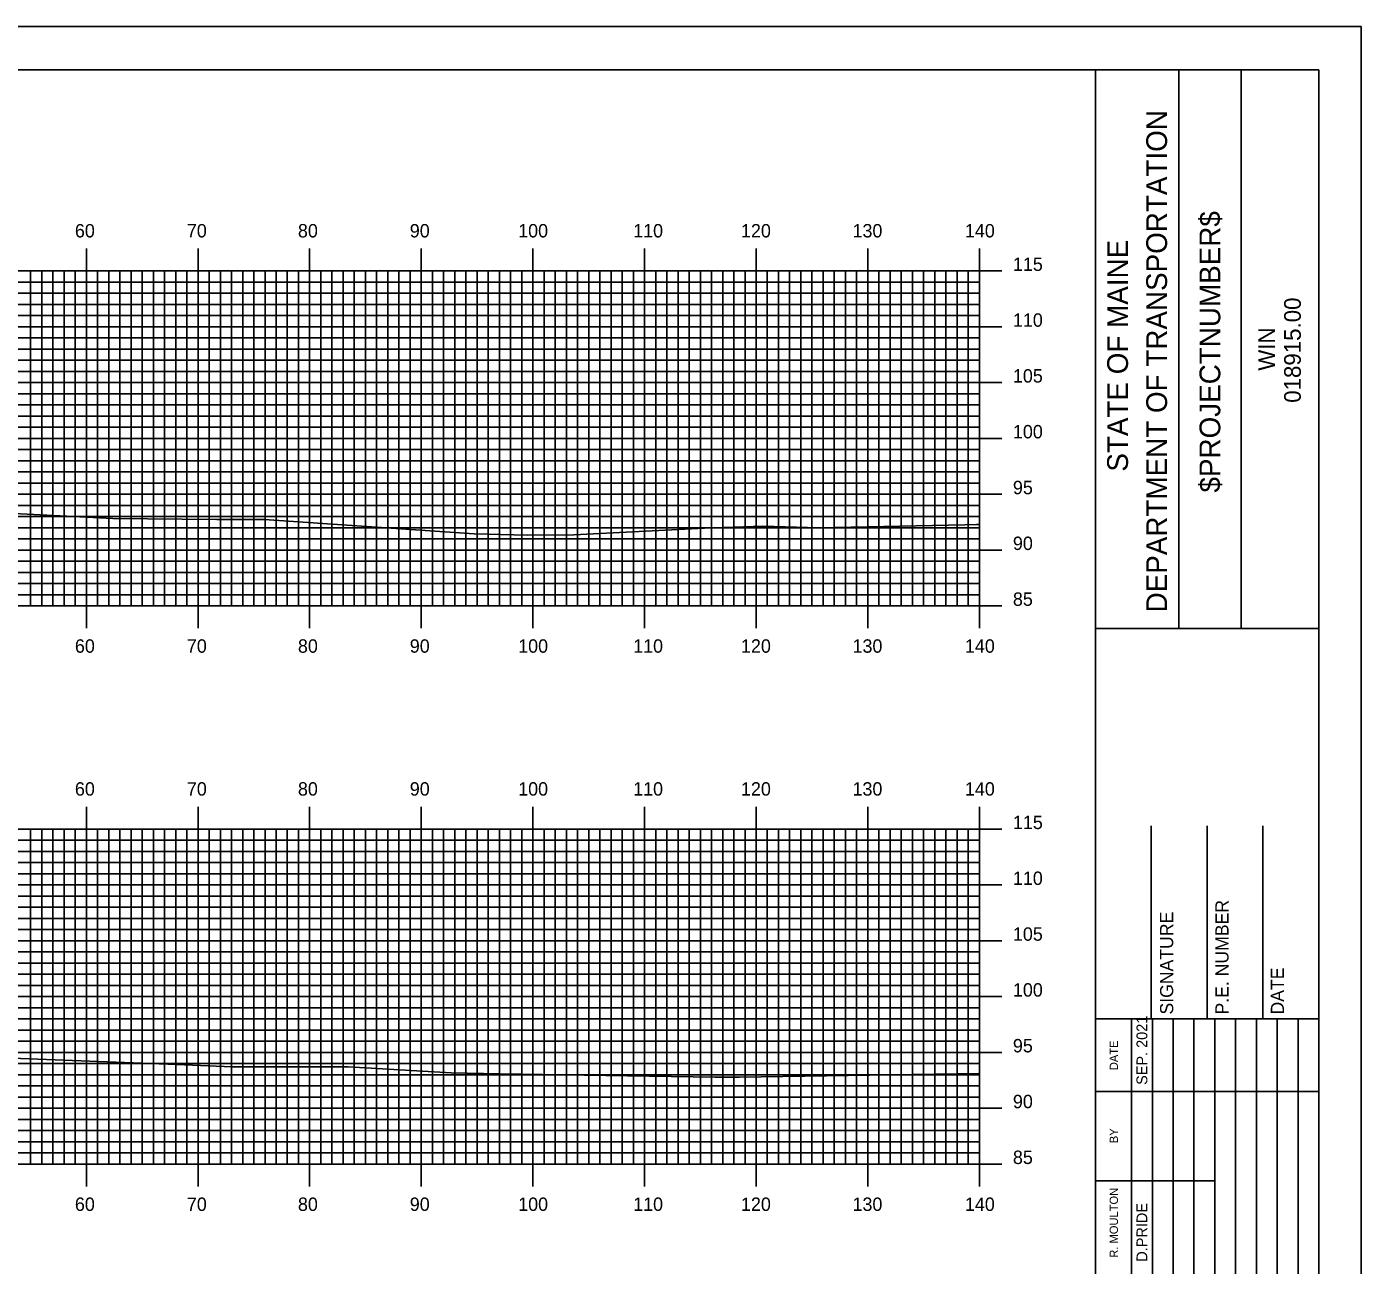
# Model space of a CAD drawing. Extents: x 1761004 to 1761347, y 442591 to 442811.
# Drawn here: x 1761224.4 to 1761343.9, y 442699.6 to 442810.5 of the extents above; entities that cross this region are included whole.
import ezdxf

# ---------------------------------------------------------------- set-up
doc = ezdxf.new("R2010")
doc.units = 0
for name, color, linetype in [('BORDER', 7, 'Continuous'), ('H_V ANNOTATION', 7, 'Continuous'), ('MAJOR', 7, 'Continuous'), ('MINOR', 7, 'Continuous'), ('PLOT BOUNDARY', 7, 'Continuous'), ('S_Roadway_Centerline', 7, 'Continuous')]:
    doc.layers.add(name, color=color, linetype=linetype)

msp = doc.modelspace()

# ---------------------------------------------------------------- linework, layer by layer
at = {"layer": 'BORDER'}
for p, q in [((1761320.13, 442596.67), (1761320.13, 442806.67)), ((1761327.58, 442756.66), (1761327.58, 442806.66)), ((1761333.17, 442756.66), (1761333.17, 442806.66)), ((1761320.13, 442756.65), (1761340.13, 442756.65)), ((1761325.13, 442721.67), (1761325.13, 442738.97)), ((1761330.13, 442721.67), (1761330.13, 442738.97)), ((1761335.13, 442721.67), (1761335.13, 442738.97)), ((1761320.13, 442721.67), (1761340.13, 442721.67))]:
    msp.add_line(p, q, dxfattribs=at)
msp.add_lwpolyline([(1761020.13, 442596.67), (1761340.13, 442596.67), (1761340.13, 442806.67), (1761020.13, 442806.67)], close=True, dxfattribs=at)
for points in [[(1761323.36, 442715.17), (1761323.36, 442721.67)], [(1761325.22, 442686.68), (1761325.22, 442721.67)], [(1761327.09, 442721.67), (1761327.09, 442686.68)], [(1761328.95, 442686.68), (1761328.95, 442721.67)], [(1761330.81, 442686.68), (1761330.81, 442721.67)], [(1761332.68, 442686.68), (1761332.68, 442721.67)], [(1761334.54, 442686.68), (1761334.54, 442721.67)], [(1761336.4, 442686.68), (1761336.4, 442721.67)], [(1761338.27, 442686.68), (1761338.27, 442721.67)], [(1761323.36, 442686.68), (1761323.36, 442720.26)], [(1761320.13, 442715.17), (1761340.13, 442715.17)], [(1761320.13, 442707.17), (1761323.36, 442707.17)], [(1761323.36, 442707.17), (1761330.81, 442707.17)]]:
    msp.add_lwpolyline(points, dxfattribs=at)
at = {"layer": 'MAJOR'}
for p, q in [((1761229.73, 442790.67), (1761229.73, 442788.67)), ((1761239.73, 442790.67), (1761239.73, 442788.67)), ((1761249.73, 442790.67), (1761249.73, 442788.67)), ((1761259.73, 442790.67), (1761259.73, 442788.67)), ((1761269.73, 442790.67), (1761269.73, 442788.67)), ((1761279.73, 442790.67), (1761279.73, 442788.67)), ((1761289.73, 442790.67), (1761289.73, 442788.67)), ((1761299.73, 442790.67), (1761299.73, 442788.67)), ((1761309.73, 442790.67), (1761309.73, 442788.67)), ((1761029.73, 442788.67), (1761309.73, 442788.67)), ((1761029.73, 442788.67), (1761309.73, 442788.67)), ((1761229.73, 442758.67), (1761229.73, 442788.67)), ((1761239.73, 442758.67), (1761239.73, 442788.67)), ((1761249.73, 442758.67), (1761249.73, 442788.67)), ((1761259.73, 442758.67), (1761259.73, 442788.67)), ((1761269.73, 442758.67), (1761269.73, 442788.67)), ((1761279.73, 442758.67), (1761279.73, 442788.67)), ((1761289.73, 442758.67), (1761289.73, 442788.67)), ((1761299.73, 442758.67), (1761299.73, 442788.67)), ((1761311.73, 442788.67), (1761307.72, 442788.67)), ((1761309.73, 442758.67), (1761309.73, 442788.67)), ((1761309.73, 442758.67), (1761309.73, 442788.67)), ((1761029.73, 442783.67), (1761309.73, 442783.67)), ((1761311.73, 442783.67), (1761307.72, 442783.67)), ((1761029.73, 442778.67), (1761309.73, 442778.67)), ((1761311.73, 442778.67), (1761307.72, 442778.67)), ((1761029.73, 442773.67), (1761309.73, 442773.67)), ((1761311.73, 442773.67), (1761307.72, 442773.67)), ((1761029.73, 442768.67), (1761309.73, 442768.67)), ((1761311.73, 442768.67), (1761307.72, 442768.67)), ((1761029.73, 442763.67), (1761309.73, 442763.67)), ((1761311.73, 442763.67), (1761307.72, 442763.67)), ((1761029.73, 442758.67), (1761309.73, 442758.67)), ((1761029.73, 442758.67), (1761309.73, 442758.67)), ((1761229.73, 442756.66), (1761229.73, 442758.67)), ((1761239.73, 442756.66), (1761239.73, 442758.67)), ((1761249.73, 442756.66), (1761249.73, 442758.67)), ((1761259.73, 442756.66), (1761259.73, 442758.67)), ((1761269.73, 442756.66), (1761269.73, 442758.67)), ((1761279.73, 442756.66), (1761279.73, 442758.67)), ((1761289.73, 442756.66), (1761289.73, 442758.67)), ((1761299.73, 442756.66), (1761299.73, 442758.67)), ((1761311.73, 442758.67), (1761307.72, 442758.67)), ((1761309.73, 442756.66), (1761309.73, 442758.67)), ((1761229.73, 442740.67), (1761229.73, 442738.67)), ((1761239.73, 442740.67), (1761239.73, 442738.67)), ((1761249.73, 442740.67), (1761249.73, 442738.67)), ((1761259.73, 442740.67), (1761259.73, 442738.67)), ((1761269.73, 442740.67), (1761269.73, 442738.67)), ((1761279.73, 442740.67), (1761279.73, 442738.67)), ((1761289.73, 442740.67), (1761289.73, 442738.67)), ((1761299.73, 442740.67), (1761299.73, 442738.67)), ((1761309.73, 442740.67), (1761309.73, 442738.67)), ((1761029.73, 442738.67), (1761309.73, 442738.67)), ((1761029.73, 442738.67), (1761309.73, 442738.67)), ((1761229.73, 442708.67), (1761229.73, 442738.67)), ((1761239.73, 442708.67), (1761239.73, 442738.67)), ((1761249.73, 442708.67), (1761249.73, 442738.67)), ((1761259.73, 442708.67), (1761259.73, 442738.67)), ((1761269.73, 442708.67), (1761269.73, 442738.67)), ((1761279.73, 442708.67), (1761279.73, 442738.67)), ((1761289.73, 442708.67), (1761289.73, 442738.67)), ((1761299.73, 442708.67), (1761299.73, 442738.67)), ((1761311.73, 442738.67), (1761307.72, 442738.67)), ((1761309.73, 442708.67), (1761309.73, 442738.67)), ((1761309.73, 442708.67), (1761309.73, 442738.67)), ((1761029.73, 442733.67), (1761309.73, 442733.67)), ((1761311.73, 442733.67), (1761307.72, 442733.67)), ((1761029.73, 442728.67), (1761309.73, 442728.67)), ((1761311.73, 442728.67), (1761307.72, 442728.67)), ((1761029.73, 442723.67), (1761309.73, 442723.67)), ((1761311.73, 442723.67), (1761307.72, 442723.67)), ((1761029.73, 442718.67), (1761309.73, 442718.67)), ((1761311.73, 442718.67), (1761307.72, 442718.67)), ((1761029.73, 442713.67), (1761309.73, 442713.67)), ((1761311.73, 442713.67), (1761307.72, 442713.67)), ((1761029.73, 442708.67), (1761309.73, 442708.67)), ((1761029.73, 442708.67), (1761309.73, 442708.67)), ((1761229.73, 442706.66), (1761229.73, 442708.67)), ((1761239.73, 442706.66), (1761239.73, 442708.67)), ((1761249.73, 442706.66), (1761249.73, 442708.67)), ((1761259.73, 442706.66), (1761259.73, 442708.67)), ((1761269.73, 442706.66), (1761269.73, 442708.67)), ((1761279.73, 442706.66), (1761279.73, 442708.67)), ((1761289.73, 442706.66), (1761289.73, 442708.67)), ((1761299.73, 442706.66), (1761299.73, 442708.67)), ((1761311.73, 442708.67), (1761307.72, 442708.67)), ((1761309.73, 442706.66), (1761309.73, 442708.67))]:
    msp.add_line(p, q, dxfattribs=at)
at = {"layer": 'MINOR'}
for p, q in [((1761224.73, 442758.67), (1761224.73, 442788.67)), ((1761225.73, 442758.67), (1761225.73, 442788.67)), ((1761226.73, 442758.67), (1761226.73, 442788.67)), ((1761227.73, 442758.67), (1761227.73, 442788.67)), ((1761228.73, 442758.67), (1761228.73, 442788.67)), ((1761230.73, 442758.67), (1761230.73, 442788.67)), ((1761231.73, 442758.67), (1761231.73, 442788.67)), ((1761232.73, 442758.67), (1761232.73, 442788.67)), ((1761233.73, 442758.67), (1761233.73, 442788.67)), ((1761234.73, 442758.67), (1761234.73, 442788.67)), ((1761235.73, 442758.67), (1761235.73, 442788.67)), ((1761236.73, 442758.67), (1761236.73, 442788.67)), ((1761237.73, 442758.67), (1761237.73, 442788.67)), ((1761238.73, 442758.67), (1761238.73, 442788.67)), ((1761240.73, 442758.67), (1761240.73, 442788.67)), ((1761241.73, 442758.67), (1761241.73, 442788.67)), ((1761242.73, 442758.67), (1761242.73, 442788.67)), ((1761243.73, 442758.67), (1761243.73, 442788.67)), ((1761244.73, 442758.67), (1761244.73, 442788.67)), ((1761245.73, 442758.67), (1761245.73, 442788.67)), ((1761246.73, 442758.67), (1761246.73, 442788.67)), ((1761247.73, 442758.67), (1761247.73, 442788.67)), ((1761248.73, 442758.67), (1761248.73, 442788.67)), ((1761250.73, 442758.67), (1761250.73, 442788.67)), ((1761251.73, 442758.67), (1761251.73, 442788.67)), ((1761252.73, 442758.67), (1761252.73, 442788.67)), ((1761253.73, 442758.67), (1761253.73, 442788.67)), ((1761254.73, 442758.67), (1761254.73, 442788.67)), ((1761255.73, 442758.67), (1761255.73, 442788.67)), ((1761256.73, 442758.67), (1761256.73, 442788.67)), ((1761257.73, 442758.67), (1761257.73, 442788.67)), ((1761258.73, 442758.67), (1761258.73, 442788.67)), ((1761260.73, 442758.67), (1761260.73, 442788.67)), ((1761261.73, 442758.67), (1761261.73, 442788.67)), ((1761262.73, 442758.67), (1761262.73, 442788.67)), ((1761263.73, 442758.67), (1761263.73, 442788.67)), ((1761264.73, 442758.67), (1761264.73, 442788.67)), ((1761265.73, 442758.67), (1761265.73, 442788.67)), ((1761266.73, 442758.67), (1761266.73, 442788.67)), ((1761267.73, 442758.67), (1761267.73, 442788.67)), ((1761268.73, 442758.67), (1761268.73, 442788.67)), ((1761270.73, 442758.67), (1761270.73, 442788.67)), ((1761271.73, 442758.67), (1761271.73, 442788.67)), ((1761272.73, 442758.67), (1761272.73, 442788.67)), ((1761273.73, 442758.67), (1761273.73, 442788.67)), ((1761274.73, 442758.67), (1761274.73, 442788.67)), ((1761275.73, 442758.67), (1761275.73, 442788.67)), ((1761276.73, 442758.67), (1761276.73, 442788.67)), ((1761277.73, 442758.67), (1761277.73, 442788.67)), ((1761278.73, 442758.67), (1761278.73, 442788.67)), ((1761280.73, 442758.67), (1761280.73, 442788.67)), ((1761281.73, 442758.67), (1761281.73, 442788.67)), ((1761282.73, 442758.67), (1761282.73, 442788.67)), ((1761283.73, 442758.67), (1761283.73, 442788.67)), ((1761284.73, 442758.67), (1761284.73, 442788.67)), ((1761285.73, 442758.67), (1761285.73, 442788.67)), ((1761286.73, 442758.67), (1761286.73, 442788.67)), ((1761287.73, 442758.67), (1761287.73, 442788.67)), ((1761288.73, 442758.67), (1761288.73, 442788.67)), ((1761290.73, 442758.67), (1761290.73, 442788.67)), ((1761291.73, 442758.67), (1761291.73, 442788.67)), ((1761292.73, 442758.67), (1761292.73, 442788.67)), ((1761293.73, 442758.67), (1761293.73, 442788.67)), ((1761294.73, 442758.67), (1761294.73, 442788.67)), ((1761295.73, 442758.67), (1761295.73, 442788.67)), ((1761296.73, 442758.67), (1761296.73, 442788.67)), ((1761297.73, 442758.67), (1761297.73, 442788.67)), ((1761298.73, 442758.67), (1761298.73, 442788.67)), ((1761300.73, 442758.67), (1761300.73, 442788.67)), ((1761301.73, 442758.67), (1761301.73, 442788.67)), ((1761302.73, 442758.67), (1761302.73, 442788.67)), ((1761303.73, 442758.67), (1761303.73, 442788.67)), ((1761304.73, 442758.67), (1761304.73, 442788.67)), ((1761305.73, 442758.67), (1761305.73, 442788.67)), ((1761306.73, 442758.67), (1761306.73, 442788.67)), ((1761307.73, 442758.67), (1761307.73, 442788.67)), ((1761308.73, 442758.67), (1761308.73, 442788.67)), ((1761029.73, 442787.67), (1761309.73, 442787.67)), ((1761309.73, 442787.67), (1761307.72, 442787.67)), ((1761029.73, 442786.67), (1761309.73, 442786.67)), ((1761309.73, 442786.67), (1761307.72, 442786.67)), ((1761029.73, 442785.67), (1761309.73, 442785.67)), ((1761309.73, 442785.67), (1761307.72, 442785.67)), ((1761029.73, 442784.67), (1761309.73, 442784.67)), ((1761309.73, 442784.67), (1761307.72, 442784.67)), ((1761029.73, 442782.67), (1761309.73, 442782.67)), ((1761309.73, 442782.67), (1761307.72, 442782.67)), ((1761029.73, 442781.67), (1761309.73, 442781.67)), ((1761309.73, 442781.67), (1761307.72, 442781.67)), ((1761029.73, 442780.67), (1761309.73, 442780.67)), ((1761309.73, 442780.67), (1761307.72, 442780.67)), ((1761029.73, 442779.67), (1761309.73, 442779.67)), ((1761309.73, 442779.67), (1761307.72, 442779.67)), ((1761029.73, 442777.67), (1761309.73, 442777.67)), ((1761309.73, 442777.67), (1761307.72, 442777.67)), ((1761029.73, 442776.67), (1761309.73, 442776.67)), ((1761309.73, 442776.67), (1761307.72, 442776.67)), ((1761029.73, 442775.67), (1761309.73, 442775.67)), ((1761309.73, 442775.67), (1761307.72, 442775.67)), ((1761029.73, 442774.67), (1761309.73, 442774.67)), ((1761309.73, 442774.67), (1761307.72, 442774.67)), ((1761029.73, 442772.67), (1761309.73, 442772.67)), ((1761029.73, 442771.67), (1761309.73, 442771.67)), ((1761309.73, 442772.67), (1761307.72, 442772.67)), ((1761309.73, 442771.67), (1761307.72, 442771.67)), ((1761029.73, 442770.67), (1761309.73, 442770.67)), ((1761309.73, 442770.67), (1761307.72, 442770.67)), ((1761029.73, 442769.67), (1761309.73, 442769.67)), ((1761309.73, 442769.67), (1761307.72, 442769.67)), ((1761029.73, 442767.67), (1761309.73, 442767.67)), ((1761309.73, 442767.67), (1761307.72, 442767.67)), ((1761029.73, 442766.67), (1761309.73, 442766.67)), ((1761029.73, 442765.67), (1761309.73, 442765.67)), ((1761309.73, 442766.67), (1761307.72, 442766.67)), ((1761309.73, 442765.67), (1761307.72, 442765.67)), ((1761029.73, 442764.67), (1761309.73, 442764.67)), ((1761309.73, 442764.67), (1761307.72, 442764.67)), ((1761029.73, 442762.67), (1761309.73, 442762.67)), ((1761309.73, 442762.67), (1761307.72, 442762.67)), ((1761029.73, 442761.67), (1761309.73, 442761.67)), ((1761309.73, 442761.67), (1761307.72, 442761.67)), ((1761029.73, 442760.67), (1761309.73, 442760.67)), ((1761029.73, 442759.67), (1761309.73, 442759.67)), ((1761309.73, 442760.67), (1761307.72, 442760.67)), ((1761309.73, 442759.67), (1761307.72, 442759.67)), ((1761224.73, 442708.67), (1761224.73, 442738.67)), ((1761225.73, 442708.67), (1761225.73, 442738.67)), ((1761226.73, 442708.67), (1761226.73, 442738.67)), ((1761227.73, 442708.67), (1761227.73, 442738.67)), ((1761228.73, 442708.67), (1761228.73, 442738.67)), ((1761230.73, 442708.67), (1761230.73, 442738.67)), ((1761231.73, 442708.67), (1761231.73, 442738.67)), ((1761232.73, 442708.67), (1761232.73, 442738.67)), ((1761233.73, 442708.67), (1761233.73, 442738.67)), ((1761234.73, 442708.67), (1761234.73, 442738.67)), ((1761235.73, 442708.67), (1761235.73, 442738.67)), ((1761236.73, 442708.67), (1761236.73, 442738.67)), ((1761237.73, 442708.67), (1761237.73, 442738.67)), ((1761238.73, 442708.67), (1761238.73, 442738.67)), ((1761240.73, 442708.67), (1761240.73, 442738.67)), ((1761241.73, 442708.67), (1761241.73, 442738.67)), ((1761242.73, 442708.67), (1761242.73, 442738.67)), ((1761243.73, 442708.67), (1761243.73, 442738.67)), ((1761244.73, 442708.67), (1761244.73, 442738.67)), ((1761245.73, 442708.67), (1761245.73, 442738.67)), ((1761246.73, 442708.67), (1761246.73, 442738.67)), ((1761247.73, 442708.67), (1761247.73, 442738.67)), ((1761248.73, 442708.67), (1761248.73, 442738.67)), ((1761250.73, 442708.67), (1761250.73, 442738.67)), ((1761251.73, 442708.67), (1761251.73, 442738.67)), ((1761252.73, 442708.67), (1761252.73, 442738.67)), ((1761253.73, 442708.67), (1761253.73, 442738.67)), ((1761254.73, 442708.67), (1761254.73, 442738.67)), ((1761255.73, 442708.67), (1761255.73, 442738.67)), ((1761256.73, 442708.67), (1761256.73, 442738.67)), ((1761257.73, 442708.67), (1761257.73, 442738.67)), ((1761258.73, 442708.67), (1761258.73, 442738.67)), ((1761260.73, 442708.67), (1761260.73, 442738.67)), ((1761261.73, 442708.67), (1761261.73, 442738.67)), ((1761262.73, 442708.67), (1761262.73, 442738.67)), ((1761263.73, 442708.67), (1761263.73, 442738.67)), ((1761264.73, 442708.67), (1761264.73, 442738.67)), ((1761265.73, 442708.67), (1761265.73, 442738.67)), ((1761266.73, 442708.67), (1761266.73, 442738.67)), ((1761267.73, 442708.67), (1761267.73, 442738.67)), ((1761268.73, 442708.67), (1761268.73, 442738.67)), ((1761270.73, 442708.67), (1761270.73, 442738.67)), ((1761271.73, 442708.67), (1761271.73, 442738.67)), ((1761272.73, 442708.67), (1761272.73, 442738.67)), ((1761273.73, 442708.67), (1761273.73, 442738.67)), ((1761274.73, 442708.67), (1761274.73, 442738.67)), ((1761275.73, 442708.67), (1761275.73, 442738.67)), ((1761276.73, 442708.67), (1761276.73, 442738.67)), ((1761277.73, 442708.67), (1761277.73, 442738.67)), ((1761278.73, 442708.67), (1761278.73, 442738.67)), ((1761280.73, 442708.67), (1761280.73, 442738.67)), ((1761281.73, 442708.67), (1761281.73, 442738.67)), ((1761282.73, 442708.67), (1761282.73, 442738.67)), ((1761283.73, 442708.67), (1761283.73, 442738.67)), ((1761284.73, 442708.67), (1761284.73, 442738.67)), ((1761285.73, 442708.67), (1761285.73, 442738.67)), ((1761286.73, 442708.67), (1761286.73, 442738.67)), ((1761287.73, 442708.67), (1761287.73, 442738.67)), ((1761288.73, 442708.67), (1761288.73, 442738.67)), ((1761290.73, 442708.67), (1761290.73, 442738.67)), ((1761291.73, 442708.67), (1761291.73, 442738.67)), ((1761292.73, 442708.67), (1761292.73, 442738.67)), ((1761293.73, 442708.67), (1761293.73, 442738.67)), ((1761294.73, 442708.67), (1761294.73, 442738.67)), ((1761295.73, 442708.67), (1761295.73, 442738.67)), ((1761296.73, 442708.67), (1761296.73, 442738.67)), ((1761297.73, 442708.67), (1761297.73, 442738.67)), ((1761298.73, 442708.67), (1761298.73, 442738.67)), ((1761300.73, 442708.67), (1761300.73, 442738.67)), ((1761301.73, 442708.67), (1761301.73, 442738.67)), ((1761302.73, 442708.67), (1761302.73, 442738.67)), ((1761303.73, 442708.67), (1761303.73, 442738.67)), ((1761304.73, 442708.67), (1761304.73, 442738.67)), ((1761305.73, 442708.67), (1761305.73, 442738.67)), ((1761306.73, 442708.67), (1761306.73, 442738.67)), ((1761307.73, 442708.67), (1761307.73, 442738.67)), ((1761308.73, 442708.67), (1761308.73, 442738.67)), ((1761029.73, 442737.67), (1761309.73, 442737.67)), ((1761309.73, 442737.67), (1761307.72, 442737.67)), ((1761029.73, 442736.67), (1761309.73, 442736.67)), ((1761309.73, 442736.67), (1761307.72, 442736.67)), ((1761029.73, 442735.67), (1761309.73, 442735.67)), ((1761029.73, 442734.67), (1761309.73, 442734.67)), ((1761309.73, 442735.67), (1761307.72, 442735.67)), ((1761309.73, 442734.67), (1761307.72, 442734.67)), ((1761029.73, 442732.67), (1761309.73, 442732.67)), ((1761309.73, 442732.67), (1761307.72, 442732.67)), ((1761029.73, 442731.67), (1761309.73, 442731.67)), ((1761309.73, 442731.67), (1761307.72, 442731.67)), ((1761029.73, 442730.67), (1761309.73, 442730.67)), ((1761309.73, 442730.67), (1761307.72, 442730.67)), ((1761029.73, 442729.67), (1761309.73, 442729.67)), ((1761309.73, 442729.67), (1761307.72, 442729.67)), ((1761029.73, 442727.67), (1761309.73, 442727.67)), ((1761309.73, 442727.67), (1761307.72, 442727.67)), ((1761029.73, 442726.67), (1761309.73, 442726.67)), ((1761309.73, 442726.67), (1761307.72, 442726.67)), ((1761029.73, 442725.67), (1761309.73, 442725.67)), ((1761309.73, 442725.67), (1761307.72, 442725.67)), ((1761029.73, 442724.67), (1761309.73, 442724.67)), ((1761309.73, 442724.67), (1761307.72, 442724.67)), ((1761029.73, 442722.67), (1761309.73, 442722.67)), ((1761309.73, 442722.67), (1761307.72, 442722.67)), ((1761029.73, 442721.67), (1761309.73, 442721.67)), ((1761309.73, 442721.67), (1761307.72, 442721.67)), ((1761029.73, 442720.67), (1761309.73, 442720.67)), ((1761309.73, 442720.67), (1761307.72, 442720.67)), ((1761029.73, 442719.67), (1761309.73, 442719.67)), ((1761309.73, 442719.67), (1761307.72, 442719.67)), ((1761029.73, 442717.67), (1761309.73, 442717.67)), ((1761029.73, 442716.67), (1761309.73, 442716.67)), ((1761309.73, 442717.67), (1761307.72, 442717.67)), ((1761309.73, 442716.67), (1761307.72, 442716.67)), ((1761029.73, 442715.67), (1761309.73, 442715.67)), ((1761309.73, 442715.67), (1761307.72, 442715.67)), ((1761029.73, 442714.67), (1761309.73, 442714.67)), ((1761309.73, 442714.67), (1761307.72, 442714.67)), ((1761029.73, 442712.67), (1761309.73, 442712.67)), ((1761309.73, 442712.67), (1761307.72, 442712.67)), ((1761029.73, 442711.67), (1761309.73, 442711.67)), ((1761029.73, 442710.67), (1761309.73, 442710.67)), ((1761309.73, 442711.67), (1761307.72, 442711.67)), ((1761309.73, 442710.67), (1761307.72, 442710.67)), ((1761029.73, 442709.67), (1761309.73, 442709.67)), ((1761309.73, 442709.67), (1761307.72, 442709.67))]:
    msp.add_line(p, q, dxfattribs=at)
at = {"layer": 'PLOT BOUNDARY'}
msp.add_lwpolyline([(1761003.94, 442590.55), (1761343.94, 442590.55), (1761343.94, 442810.55), (1761003.94, 442810.55)], close=True, dxfattribs=at)
at = {"layer": 'S_Roadway_Centerline'}
for points in [[(1761221.43, 442767.02), (1761232.1, 442766.5), (1761241.42, 442766.4), (1761243.37, 442766.4), (1761245.65, 442766.39), (1761264.47, 442765.11), (1761269.22, 442764.99), (1761273.39, 442765.02), (1761285.1, 442765.64), (1761290.34, 442765.82), (1761295.34, 442765.67), (1761308.41, 442765.93), (1761309.47, 442765.96), (1761309.73, 442765.95)], [(1761221.47, 442718.21), (1761237.8, 442717.59), (1761242.8, 442717.39), (1761253.19, 442717.39), (1761262.4, 442716.83), (1761266.75, 442716.76), (1761276.26, 442716.6), (1761286.03, 442716.46), (1761288.23, 442716.45), (1761309.66, 442716.79), (1761309.73, 442716.79)]]:
    msp.add_lwpolyline(points, dxfattribs=at)

# ---------------------------------------------------------------- texts
at = {"layer": 'BORDER'}
for s, height, p in [('DEPARTMENT OF TRANSPORTATION', 1.8635, (1761326.54, 442758.08)), ('$PROJECTNUMBER$', 1.8635, (1761331.31, 442768.82)), ('STATE OF MAINE', 1.8635, (1761323.04, 442770.69)), ('018915.00', 1.491, (1761338.52, 442776.86)), ('WIN', 1.491, (1761336.2, 442779.73)), ('P.E. NUMBER', 1.1811, (1761332.05, 442722.06)), ('SIGNATURE', 1.181, (1761327.09, 442722.06)), ('DATE', 1.181, (1761337.01, 442722.06)), ('SEP. 2021', 0.969, (1761324.77, 442715.76)), ('DATE', 0.743, (1761322.14, 442717.08)), ('BY', 0.743, (1761322.14, 442710.54)), ('R. MOULTON', 0.745, (1761322.14, 442700.28)), ('D.PRIDE', 0.969, (1761324.77, 442699.92))]:
    msp.add_text(s, height=height, rotation=90, dxfattribs=at).set_placement(p)
at = {"layer": 'H_V ANNOTATION'}
for s, p in [('60', (1761228.7, 442791.67)), ('70', (1761238.73, 442791.67)), ('80', (1761248.68, 442791.67)), ('90', (1761258.7, 442791.67)), ('100', (1761268.41, 442791.67)), ('110', (1761278.71, 442791.67)), ('120', (1761288.37, 442791.67)), ('130', (1761298.36, 442791.67)), ('140', (1761308.43, 442791.67)), ('115', (1761312.73, 442788.67)), ('110', (1761312.73, 442783.67)), ('105', (1761312.73, 442778.67)), ('100', (1761312.73, 442773.67)), ('95', (1761312.73, 442768.67)), ('90', (1761312.73, 442763.67)), ('85', (1761312.73, 442758.67)), ('60', (1761228.7, 442754.47)), ('70', (1761238.73, 442754.47)), ('80', (1761248.68, 442754.47)), ('90', (1761258.7, 442754.47)), ('100', (1761268.41, 442754.47)), ('110', (1761278.71, 442754.47)), ('120', (1761288.37, 442754.47)), ('130', (1761298.36, 442754.47)), ('140', (1761308.43, 442754.47)), ('60', (1761228.7, 442741.67)), ('70', (1761238.73, 442741.67)), ('80', (1761248.68, 442741.67)), ('90', (1761258.7, 442741.67)), ('100', (1761268.41, 442741.67)), ('110', (1761278.71, 442741.67)), ('120', (1761288.37, 442741.67)), ('130', (1761298.36, 442741.67)), ('140', (1761308.43, 442741.67)), ('115', (1761312.73, 442738.67)), ('110', (1761312.73, 442733.67)), ('105', (1761312.73, 442728.67)), ('100', (1761312.73, 442723.67)), ('95', (1761312.73, 442718.67)), ('90', (1761312.73, 442713.67)), ('85', (1761312.73, 442708.67)), ('60', (1761228.7, 442704.47)), ('70', (1761238.73, 442704.47)), ('80', (1761248.68, 442704.47)), ('90', (1761258.7, 442704.47)), ('100', (1761268.41, 442704.47)), ('110', (1761278.71, 442704.47)), ('120', (1761288.37, 442704.47)), ('130', (1761298.36, 442704.47)), ('140', (1761308.43, 442704.47))]:
    msp.add_text(s, height=1.2, dxfattribs=at).set_placement(p)

doc.saveas('drawing.dxf')
